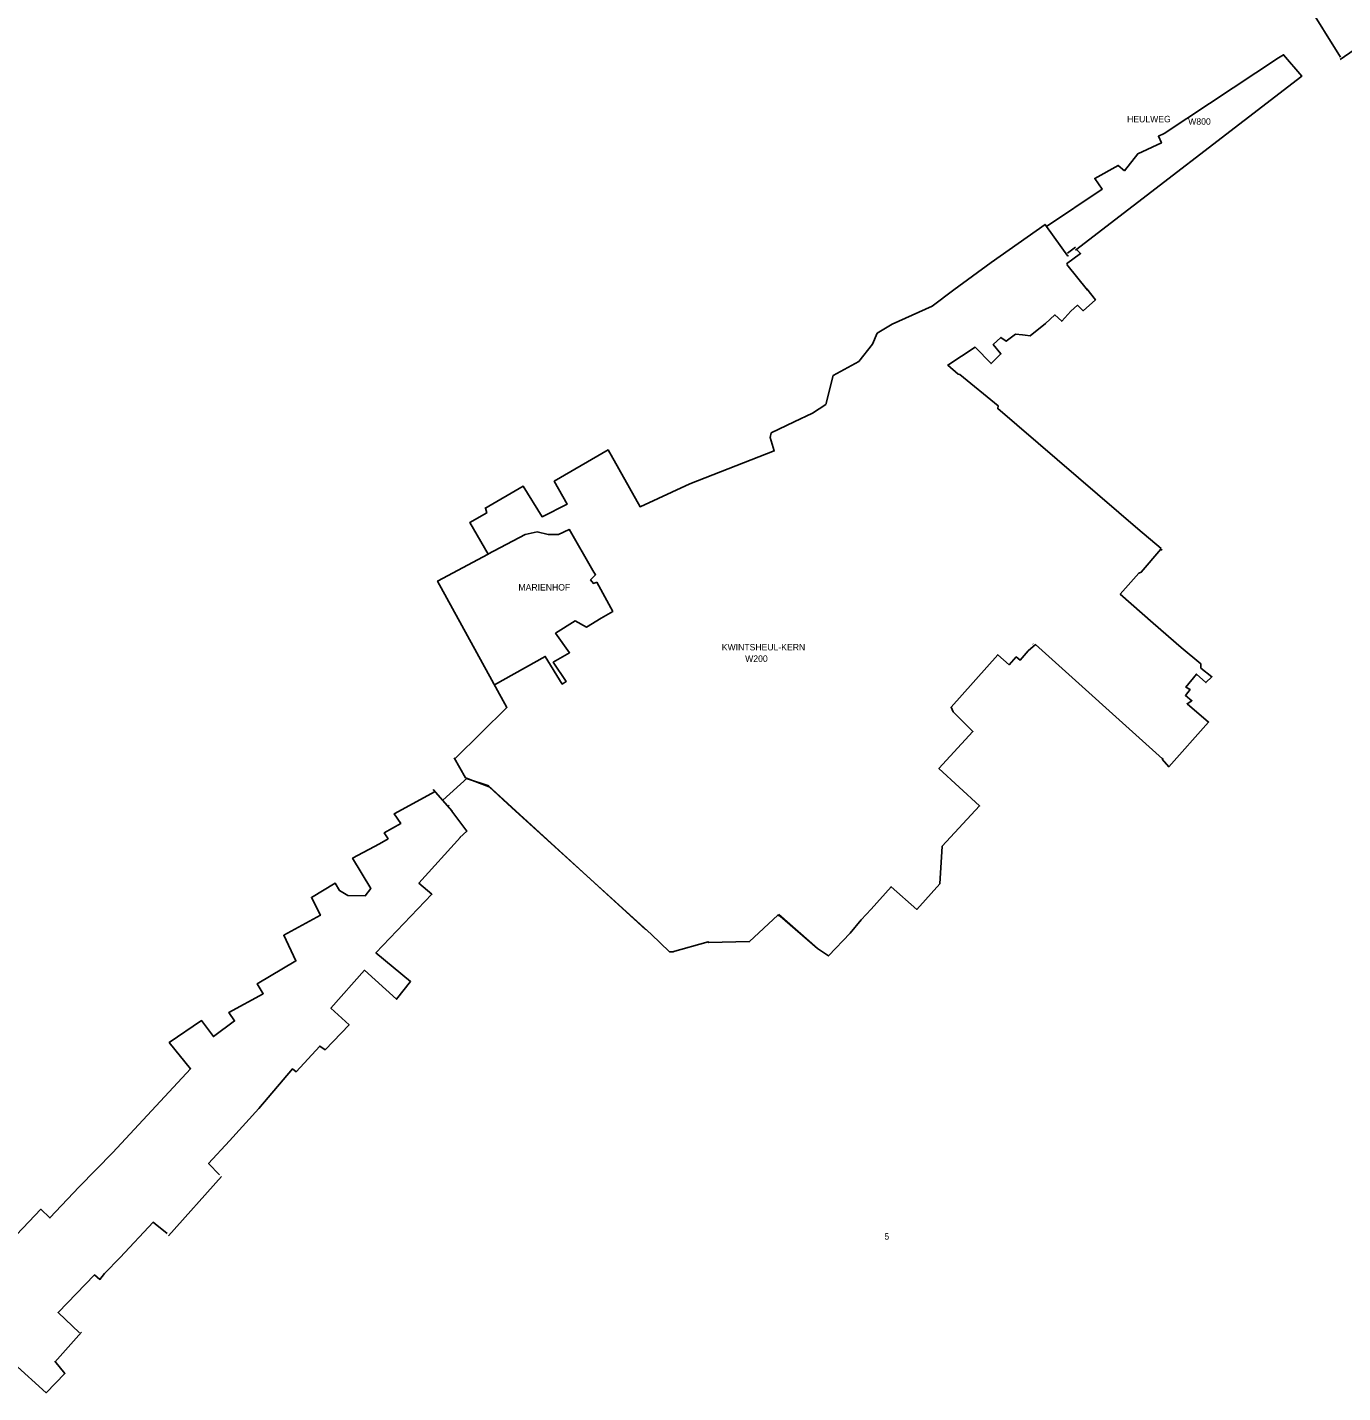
# Model space of a CAD drawing. Extents: x 69068 to 80855, y 440023 to 451362.
# Drawn here: x 76267 to 78102, y 446828 to 448732 of the extents above; entities that cross this region are included whole.
import ezdxf

# ---------------------------------------------------------------- set-up
doc = ezdxf.new("R2010")
doc.units = 0
for name, color, linetype in [('Bemalingsgebiedsgrens', 7, 'Continuous'), ('Bemalingsgebiedsnummer', 7, 'Continuous'), ('RIO_Leidingen', 7, 'Continuous')]:
    doc.layers.add(name, color=color, linetype=linetype)

msp = doc.modelspace()

# ---------------------------------------------------------------- linework, layer by layer
at = {"layer": 'Bemalingsgebiedsgrens'}
for p, q in [((77688.6, 448454.3), (77718.3, 448413.1)), ((77688.6, 448454.3), (77718.3, 448413.1)), ((77717.8, 448416.9), (77728.9, 448425.6)), ((77717.8, 448416.9), (77728.9, 448425.6)), ((77745.9, 448365.4), (77716.9, 448401.3)), ((77745.9, 448365.4), (77716.9, 448401.3)), ((76846.8, 447654.1), (76881.1, 447685.6)), ((76881.1, 447684), (76910.9, 447674)), ((76881.1, 447684), (76910.9, 447674)), ((76910.1, 447674.7), (77129.8, 447473.2)), ((76910.1, 447674.7), (77129.8, 447473.2)), ((77313.9, 447493.5), (77315.4, 447494.9)), ((77313.9, 447493.5), (77315.4, 447494.9)), ((77315.4, 447494.9), (77314.9, 447494.5)), ((77315.4, 447494.9), (77314.9, 447494.5)), ((77369.2, 447447.3), (77315.4, 447494.9)), ((77369.2, 447447.3), (77315.4, 447494.9))]:
    msp.add_line(p, q, dxfattribs=at)
for points in [[(78098.4, 448690.2), (78051.7, 448765.9), (77997.1, 448860.5), (77962.7, 448930.9), (77885.3, 449114), (77799.9, 449314.1), (77767.6, 449379.1)], [(78117.5, 448700.6), (78098.1, 448687.3)], [(77797.5, 448532.1), (77815.9, 448555.8), (77848.9, 448570.8), (77844.7, 448580.1), (77852.9, 448583.8), (78011.9, 448689.7), (78019.3, 448693.8), (78044.6, 448663.7), (77729.1, 448421.3)], [(77797.5, 448532.1), (77815.9, 448555.8), (77848.9, 448570.8), (77844.7, 448580.1), (77852.9, 448583.8), (78011.9, 448689.7), (78019.3, 448693.8), (78044.6, 448663.7), (77729.1, 448421.3)], [(77452.3, 448305.3), (77473.3, 448318), (77529, 448343.1), (77559.2, 448366.1), (77611.3, 448403.9), (77686.6, 448457.2), (77688.6, 448454.3), (77766, 448506.2), (77755.9, 448521.3), (77788.3, 448539.5), (77797.5, 448532.1)], [(77452.3, 448305.3), (77473.3, 448318), (77529, 448343.1), (77559.2, 448366.1), (77611.3, 448403.9), (77686.6, 448457.2), (77688.6, 448454.3), (77766, 448506.2), (77755.9, 448521.3), (77788.3, 448539.5), (77797.5, 448532.1)], [(77716.3, 448402.2), (77736.1, 448416.5), (77729.8, 448422.8)], [(77716.3, 448402.2), (77736.1, 448416.5), (77729.8, 448422.8)], [(77719.4, 448413.9), (77718.3, 448413)], [(77719.4, 448413.9), (77718.3, 448413)], [(77848.3, 448005.1), (77815.8, 448032.7), (77620.6, 448200.4), (77621.1, 448204.3), (77567.9, 448247.8), (77565.4, 448248.3), (77550.8, 448261), (77589.3, 448285.9), (77611.3, 448263), (77625, 448276.6), (77614.2, 448289.8), (77625, 448299.6), (77632.3, 448294.2), (77645.5, 448304), (77654.9, 448303.3), (77659, 448302.8), (77666, 448302), (77687, 448319.1), (77700.2, 448330.9), (77709.9, 448322.1), (77722.6, 448336.2), (77731.9, 448344.5), (77739.7, 448336.7), (77756.8, 448351.9), (77744.6, 448367.5)], [(77848.3, 448005.1), (77815.8, 448032.7), (77620.6, 448200.4), (77621.1, 448204.3), (77567.9, 448247.8), (77565.4, 448248.3), (77550.8, 448261), (77589.3, 448285.9), (77611.3, 448263), (77625, 448276.6), (77614.2, 448289.8), (77625, 448299.6), (77632.3, 448294.2), (77645.5, 448304), (77654.9, 448303.3), (77659, 448302.8), (77666, 448302), (77687, 448319.1), (77700.2, 448330.9), (77709.9, 448322.1), (77722.6, 448336.2), (77731.9, 448344.5), (77739.7, 448336.7), (77756.8, 448351.9), (77744.6, 448367.5)], [(76905.3, 448060.9), (76958.8, 448092), (76985, 448049.5), (77020.2, 448067.2), (77002.1, 448099.1), (77077.1, 448142.7), (77121.7, 448063.5), (77191.3, 448095.6), (77308.9, 448141.2), (77303.3, 448160.2), (77304.8, 448166.3), (77336.5, 448181.7), (77362, 448193.8), (77380.9, 448206.1), (77391.1, 448246.6), (77426.9, 448266), (77445.8, 448290), (77452.3, 448305.3)], [(76905.3, 448060.9), (76958.8, 448092), (76985, 448049.5), (77020.2, 448067.2), (77002.1, 448099.1), (77077.1, 448142.7), (77121.7, 448063.5), (77191.3, 448095.6), (77308.9, 448141.2), (77303.3, 448160.2), (77304.8, 448166.3), (77336.5, 448181.7), (77362, 448193.8), (77380.9, 448206.1), (77391.1, 448246.6), (77426.9, 448266), (77445.8, 448290), (77452.3, 448305.3)], [(76864.3, 447713), (76936.1, 447783.5), (76839.4, 447959.7), (76909.9, 447997.2), (76884.1, 448041.4), (76907.9, 448054.9), (76906.1, 448061.5)], [(76864.3, 447713), (76936.1, 447783.5), (76839.4, 447959.7), (76909.9, 447997.2), (76884.1, 448041.4), (76907.9, 448054.9), (76906.1, 448061.5)], [(76909.2, 447997.5), (76961.5, 448024.8), (76978.2, 448028.3), (76993.6, 448024.8), (77007.9, 448024.8), (77022.9, 448031.8)], [(76909.2, 447997.5), (76961.5, 448024.8), (76978.2, 448028.3), (76993.6, 448024.8), (77007.9, 448024.8), (77022.9, 448031.8)], [(77022.8, 448032), (77055.7, 447974.7), (77059.8, 447968.5), (77052.6, 447961.3), (77056.7, 447956.4), (77061.2, 447958.2)], [(77022.8, 448032), (77055.7, 447974.7), (77059.8, 447968.5), (77052.6, 447961.3), (77056.7, 447956.4), (77061.2, 447958.2)], [(77850.1, 448002.7), (77848, 448004.4), (77820.8, 447972), (77817.2, 447970.8), (77791.5, 447941.6), (77837.4, 447900.9), (77876.5, 447867.3), (77903.8, 447844.4), (77903.8, 447838.5), (77919.3, 447826.3), (77911, 447818.2), (77897.6, 447830), (77882.8, 447812), (77888.7, 447808.5), (77882.2, 447800.2), (77891.3, 447792.9), (77884.6, 447788.7), (77914.6, 447763.1), (77859.1, 447700.9), (77849.7, 447711.2)], [(77850.1, 448002.7), (77848, 448004.4), (77820.8, 447972), (77817.2, 447970.8), (77791.5, 447941.6), (77837.4, 447900.9), (77876.5, 447867.3), (77903.8, 447844.4), (77903.8, 447838.5), (77919.3, 447826.3), (77911, 447818.2), (77897.6, 447830), (77882.8, 447812), (77888.7, 447808.5), (77882.2, 447800.2), (77891.3, 447792.9), (77884.6, 447788.7), (77914.6, 447763.1), (77859.1, 447700.9), (77849.7, 447711.2)], [(77061.2, 447958.2), (77083.6, 447917.5), (77067.7, 447908), (77046.9, 447895.6), (77031.4, 447904.1), (77003.8, 447886.9), (77023.5, 447859.8), (77000.7, 447846.6), (77018.6, 447819.5), (77013.1, 447816.1), (76989.4, 447854.7), (76918.5, 447815.2)], [(77061.2, 447958.2), (77083.6, 447917.5), (77067.7, 447908), (77046.9, 447895.6), (77031.4, 447904.1), (77003.8, 447886.9), (77023.5, 447859.8), (77000.7, 447846.6), (77018.6, 447819.5), (77013.1, 447816.1), (76989.4, 447854.7), (76918.5, 447815.2)], [(77851.4, 447713), (77850.5, 447712), (77673.1, 447871.1), (77662.9, 447862.4), (77651.7, 447849.3), (77646.3, 447854.1), (77636.3, 447843.1), (77620.5, 447857.1), (77555.4, 447783.9), (77558.6, 447777.6), (77585.9, 447750), (77538.5, 447698.2), (77595.3, 447646.3), (77543.2, 447589.9), (77539.6, 447537.5), (77507.6, 447501.8), (77471.8, 447533.5), (77444.2, 447502.2), (77430, 447487.2), (77414.6, 447468.6), (77384.4, 447437), (77369.2, 447447.3)], [(77851.4, 447713), (77850.5, 447712), (77673.1, 447871.1), (77662.9, 447862.4), (77651.7, 447849.3), (77646.3, 447854.1), (77636.3, 447843.1), (77620.5, 447857.1), (77555.4, 447783.9), (77558.6, 447777.6), (77585.9, 447750), (77538.5, 447698.2), (77595.3, 447646.3), (77543.2, 447589.9), (77539.6, 447537.5), (77507.6, 447501.8), (77471.8, 447533.5), (77444.2, 447502.2), (77430, 447487.2), (77414.6, 447468.6), (77384.4, 447437), (77369.2, 447447.3)], [(77669.9, 447871.8), (77669.3, 447872.4)], [(77669.9, 447871.8), (77669.3, 447872.4)], [(77168.5, 447442.6), (77162.8, 447442.8), (77137.2, 447467.2), (76942.7, 447643.6), (76911.1, 447672.9), (76878.3, 447685.5), (76862.5, 447713.3)], [(77168.5, 447442.6), (77162.8, 447442.8), (77137.2, 447467.2), (76942.7, 447643.6), (76911.1, 447672.9), (76878.3, 447685.5), (76862.5, 447713.3)], [(76235.5, 447030.2), (76286.2, 447083.7), (76298.6, 447071.7), (76339.4, 447115.2), (76386.5, 447162.9), (76494.8, 447279.6), (76465.2, 447316.1), (76510.3, 447346.9), (76526.7, 447324.5), (76556.1, 447346.3), (76548, 447358), (76596.2, 447384.3), (76587.7, 447397.9), (76641.7, 447430), (76624.8, 447465.8), (76676, 447493.8), (76663.3, 447518.7), (76696.6, 447538.4), (76702.4, 447528.1), (76714, 447521.2), (76738.4, 447520.9), (76746.2, 447530.9), (76720.7, 447573.3), (76758.1, 447593.5), (76770.3, 447600.4), (76765, 447608.5), (76788, 447621.8), (76778.8, 447635.4), (76835.9, 447666.1)], [(76833, 447669.1), (76859.5, 447638.7)], [(76855.6, 447647.2), (76853.9, 447645.7)], [(76859.2, 447639), (76880.3, 447611.2), (76870.3, 447602.1)], [(76871.4, 447602.8), (76813.2, 447538.5), (76831.5, 447523), (76753.4, 447441.5), (76801.6, 447401.2), (76782.2, 447376.5), (76737.3, 447417), (76690.5, 447364.1), (76715.9, 447340.8), (76682.7, 447306.2), (76674.9, 447311.2), (76642.2, 447275.4), (76637, 447279.6), (76589.9, 447224.4), (76548.9, 447179.3), (76520, 447147.7), (76535, 447131.9)], [(77369.2, 447447.3), (77317.3, 447492.6), (77313.7, 447494), (77274.4, 447457.1), (77217.1, 447455.7), (77216.7, 447456.8), (77167.1, 447442.5)], [(77369.2, 447447.3), (77317.3, 447492.6), (77313.7, 447494), (77274.4, 447457.1), (77217.1, 447455.7), (77216.7, 447456.8), (77167.1, 447442.5)], [(76538.2, 447129.4), (76464, 447046.8)], [(76462.1, 447050.1), (76445.5, 447063.4), (76442.5, 447065.6), (76396.5, 447016.6), (76374.6, 446994.2), (76368.5, 446985.8), (76361, 446992.2), (76310, 446939.6), (76339.9, 446911.3)], [(76342.9, 446912.1), (76305.4, 446870.4)], [(76305.6, 446871.9), (76319.7, 446854.8), (76293.4, 446827.9), (76248.2, 446868.6)]]:
    msp.add_lwpolyline(points, dxfattribs=at)

# ---------------------------------------------------------------- texts
at = {"layer": 'Bemalingsgebiedsnummer'}
for s, p in [('W800', (77886.2, 448596.2)), ('W800', (77886.2, 448596.2)), ('W200', (77268.3, 447847.1)), ('W200', (77268.3, 447847.1))]:
    msp.add_text(s, height=9, dxfattribs=at).set_placement(p)
msp.add_text('5', height=9, rotation=1.5, dxfattribs=at).set_placement((77462.6, 447041.3))
at = {"layer": 'RIO_Leidingen'}
for s, p in [('HEULWEG', (77801, 448599.6)), ('HEULWEG', (77801, 448599.6)), ('MARIENHOF', (76952.1, 447946.6)), ('MARIENHOF', (76952.1, 447946.6)), ('KWINTSHEUL-KERN', (77235.7, 447863.1)), ('KWINTSHEUL-KERN', (77235.7, 447863.1))]:
    msp.add_text(s, height=9, dxfattribs=at).set_placement(p)

doc.saveas('drawing.dxf')
